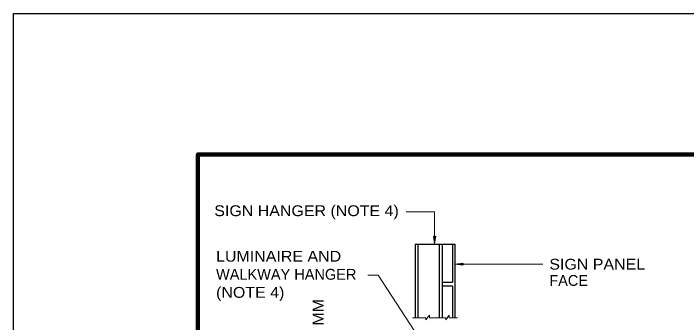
# Model space of a CAD drawing. Extents: x 312601.858 to 312602.699, y 144420.109 to 144420.704.
# Drawn here: x 312601.8578 to 312602.0438, y 144420.6179 to 144420.7035 of the extents above; entities that cross this region are included whole.
import ezdxf
from ezdxf.enums import TextEntityAlignment as Align

# ---------------------------------------------------------------- set-up
doc = ezdxf.new("R2010")
doc.units = 0
doc.header["$LTSCALE"] = 0.0012
for name, color, linetype, lineweight in [('1', 7, 'Continuous', 13), ('2', 7, 'Continuous', 13), ('39', 7, 'Continuous', 13)]:
    doc.layers.add(name, color=color, linetype=linetype, lineweight=lineweight)

msp = doc.modelspace()

# ---------------------------------------------------------------- linework, layer by layer
at = {"layer": '1'}
for p, q in [((312601.9742, 144420.6486), (312601.9663, 144420.6486)), ((312601.9742, 144420.6486), (312601.9742, 144420.6396)), ((312601.9798, 144420.6341), (312602.0041, 144420.6341)), ((312601.9586, 144420.6311), (312601.9557, 144420.6311)), ((312601.9586, 144420.6311), (312601.9724, 144420.6098)), ((312601.9681, 144420.6193), (312601.9718, 144420.6193)), ((312601.9718, 144420.6187), (312601.9728, 144420.62)), ((312601.9718, 144420.6187), (312601.9718, 144420.6193)), ((312601.9728, 144420.6193), (312601.9728, 144420.62)), ((312601.9728, 144420.6193), (312601.9773, 144420.6193)), ((312601.9773, 144420.6187), (312601.9782, 144420.62)), ((312601.9773, 144420.6187), (312601.9773, 144420.6193)), ((312601.9782, 144420.6193), (312601.9782, 144420.62)), ((312601.9782, 144420.6193), (312601.9805, 144420.6193))]:
    msp.add_line(p, q, dxfattribs=at)
at = {"layer": '1', "lineweight": 25}
for p, q in [((312601.9688, 144420.6396), (312601.9798, 144420.6396)), ((312601.9688, 144420.6396), (312601.9688, 144420.6193)), ((312601.9696, 144420.6396), (312601.9696, 144420.6193)), ((312601.9755, 144420.6396), (312601.9755, 144420.6193)), ((312601.9763, 144420.6396), (312601.9763, 144420.6193)), ((312601.9791, 144420.6396), (312601.9791, 144420.6291)), ((312601.9798, 144420.6396), (312601.9798, 144420.6193)), ((312601.9763, 144420.6291), (312601.9791, 144420.6291)), ((312601.9763, 144420.6281), (312601.9791, 144420.6281)), ((312601.9791, 144420.6281), (312601.9791, 144420.6193))]:
    msp.add_line(p, q, dxfattribs=at)
at = {"layer": '1'}
for points in [[(312601.9745, 144420.6419), (312601.9742, 144420.6396), (312601.9739, 144420.6419), (312601.9742, 144420.6416)], [(312601.9821, 144420.6338), (312601.9798, 144420.6341), (312601.9821, 144420.6344), (312601.9818, 144420.6341)]]:
    msp.add_lwpolyline(points, close=True, dxfattribs=at)
at = {"layer": '39', "lineweight": 25}
for p, q in [((312601.8578, 144420.7035), (312602.6988, 144420.7035)), ((312601.8578, 144420.1095), (312601.8578, 144420.7035))]:
    msp.add_line(p, q, dxfattribs=at)
at = {"layer": '39', "lineweight": 158}
msp.add_lwpolyline([(312601.9088, 144420.1247), (312601.9088, 144420.6645), (312602.6838, 144420.6645)], dxfattribs=at)

# ---------------------------------------------------------------- texts
at = {"layer": '2', "width": 1.1}
msp.add_text('SIGN HANGER (NOTE 4)', height=0.003, dxfattribs=at).set_placement((312601.9388, 144420.6474), align=Align.CENTER)
for s, p in [('LUMINAIRE AND', (312601.9138, 144420.6348)), ('SIGN PANEL', (312602.0059, 144420.6326)), ('(NOTE 4)', (312601.9138, 144420.6248))]:
    msp.add_text(s, height=0.003, dxfattribs=at).set_placement(p)
at = {"layer": '2'}
for s, p in [('WALKWAY HANGER', (312601.9138, 144420.6298)), ('FACE', (312602.0059, 144420.6281))]:
    msp.add_text(s, height=0.003, dxfattribs=at).set_placement(p)
at = {"layer": '2', "width": 1.1}
msp.add_text('75 MM', height=0.003, rotation=90, dxfattribs=at).set_placement((312601.9435, 144420.61775), align=Align.CENTER)

doc.saveas('drawing.dxf')
